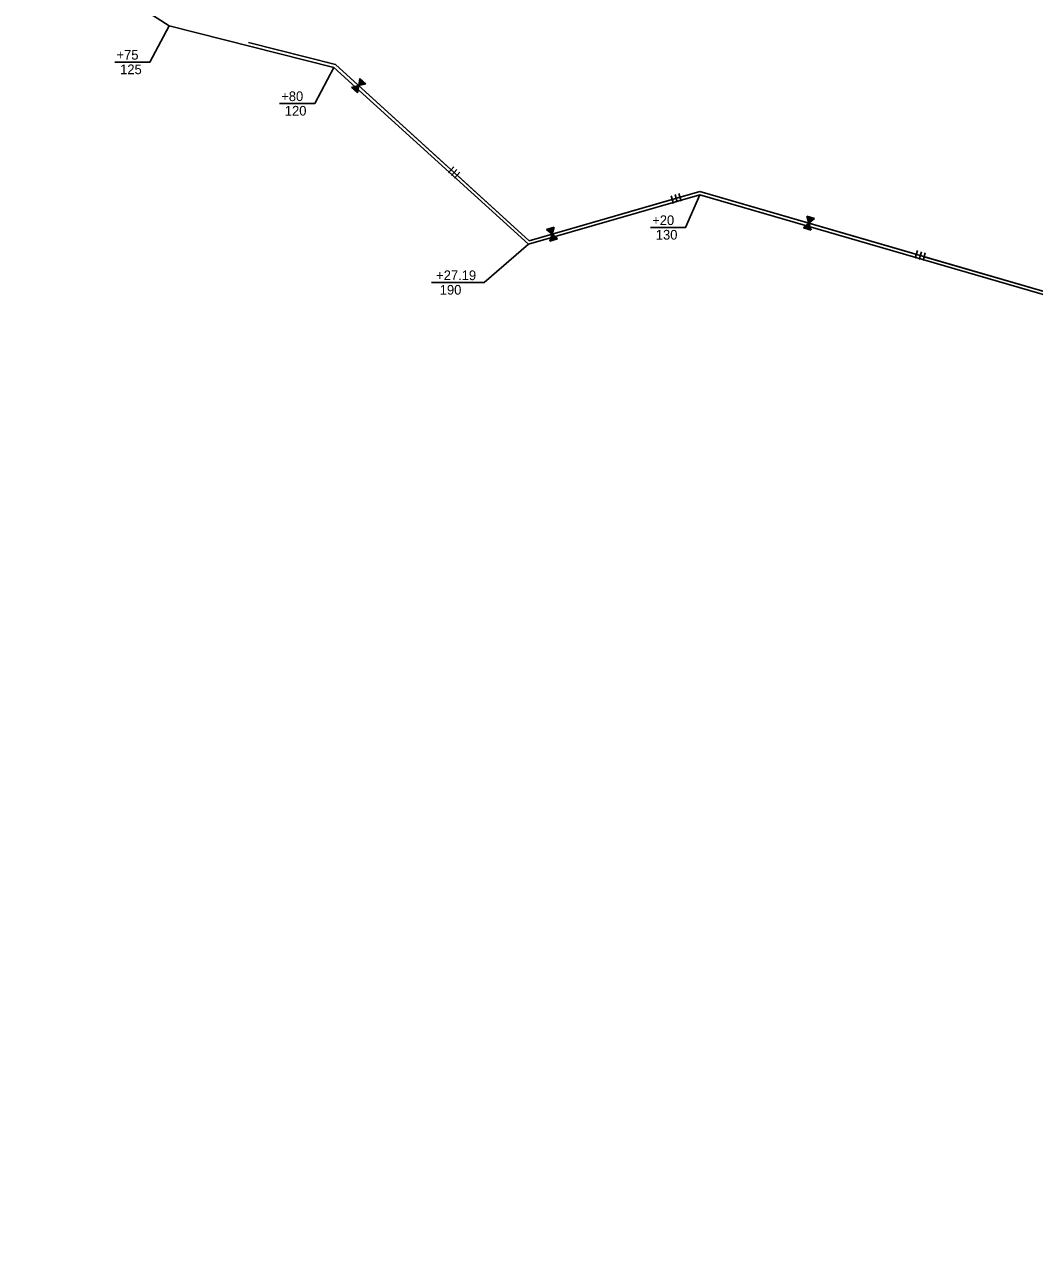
# Model space of a CAD drawing. Extents: x 979729 to 993523, y 1834148 to 1845433.
# Drawn here: x 981272 to 981898, y 1837610 to 1838364 of the extents above; entities that cross this region are included whole.
import ezdxf

# ---------------------------------------------------------------- set-up
doc = ezdxf.new("R2010")
doc.units = 0
for name, color, linetype in [('42', 7, 'Continuous'), ('51', 7, 'Continuous'), ('R_Draft', 7, 'Continuous')]:
    doc.layers.add(name, color=color, linetype=linetype)

msp = doc.modelspace()

# ---------------------------------------------------------------- linework, layer by layer
at = {"layer": '42'}
for p, q in [((981411.34, 1838352.61), (981465.14, 1838339.09)), ((981465.14, 1838339.09), (981585.3, 1838229.88)), ((981475.22, 1838324.86), (981479.59, 1838325.95)), ((981475.82, 1838324.99), (981475.73, 1838324.39)), ((981476.08, 1838325.04), (981475.95, 1838324.19)), ((981476.35, 1838325.12), (981476.18, 1838323.99)), ((981476.61, 1838325.21), (981476.4, 1838323.78)), ((981476.87, 1838325.25), (981476.62, 1838323.58)), ((981477.12, 1838325.24), (981476.87, 1838323.55)), ((981477.39, 1838325.36), (981477.06, 1838323.18)), ((981477.65, 1838325.4), (981477.29, 1838322.98)), ((981477.92, 1838325.52), (981477.51, 1838322.77)), ((981478.18, 1838325.53), (981477.73, 1838322.57)), ((981478.45, 1838325.65), (981477.95, 1838322.37)), ((981478.71, 1838325.69), (981478.18, 1838322.17)), ((981478.97, 1838325.78), (981478.4, 1838321.97)), ((981479.23, 1838325.8), (981478.62, 1838321.76)), ((981479.5, 1838325.91), (981478.84, 1838321.56)), ((981479.59, 1838325.95), (981478.92, 1838321.5)), ((981480.26, 1838330.41), (981479.59, 1838325.95)), ((981479.59, 1838325.95), (981483.96, 1838327.05)), ((981479.62, 1838326.05), (981483.89, 1838327.11)), ((981479.7, 1838326.58), (981483.44, 1838327.52)), ((981479.71, 1838326.33), (981483.67, 1838327.31)), ((981479.76, 1838326.85), (981483.22, 1838327.72)), ((981479.78, 1838327.12), (981483, 1838327.92)), ((981479.86, 1838327.65), (981482.55, 1838328.32)), ((981479.87, 1838327.4), (981482.78, 1838328.12)), ((981479.95, 1838327.93), (981482.33, 1838328.53)), ((981479.97, 1838328.19), (981482.11, 1838328.73)), ((981480.03, 1838328.72), (981481.66, 1838329.13)), ((981480.05, 1838328.99), (981481.44, 1838329.33)), ((981480.07, 1838328.48), (981481.73, 1838328.89)), ((981480.11, 1838329.26), (981481.22, 1838329.54)), ((981480.17, 1838329.53), (981481, 1838329.74)), ((981480.19, 1838329.79), (981480.78, 1838329.94)), ((981480.25, 1838330.07), (981480.55, 1838330.14)), ((981480.27, 1838330.33), (981480.33, 1838330.35)), ((981475.3, 1838324.86), (981475.29, 1838324.8)), ((981475.56, 1838324.91), (981475.51, 1838324.59)), ((981538.62, 1838275.68), (981535.26, 1838271.98)), ((981540.47, 1838274), (981537.11, 1838270.3)), ((981542.32, 1838272.31), (981538.96, 1838268.61)), ((981585.3, 1838229.88), (981690.99, 1838260.28)), ((981673.17, 1838257.76), (981674.55, 1838252.96)), ((981675.57, 1838258.45), (981676.96, 1838253.65)), ((981677.98, 1838259.14), (981679.36, 1838254.34)), ((981690.99, 1838260.28), (982114.9, 1838137.28)), ((981757.2, 1838244.98), (981758.56, 1838240.68)), ((981757.24, 1838244.91), (981757.29, 1838244.95)), ((981757.34, 1838244.66), (981757.58, 1838244.87)), ((981757.41, 1838244.39), (981757.87, 1838244.78)), ((981757.5, 1838244.15), (981758.16, 1838244.7)), ((981757.57, 1838243.87), (981758.45, 1838244.61)), ((981757.64, 1838243.6), (981758.74, 1838244.53)), ((981757.73, 1838243.36), (981759.02, 1838244.45)), ((981757.88, 1838243.16), (981759.19, 1838244.26)), ((981757.92, 1838242.86), (981759.6, 1838244.28)), ((981758.01, 1838242.61), (981759.89, 1838244.2)), ((981758.06, 1838242.33), (981760.18, 1838244.11)), ((981758.18, 1838242.1), (981760.47, 1838244.03)), ((981758.22, 1838241.81), (981760.76, 1838243.94)), ((981758.32, 1838241.57), (981761.04, 1838243.86)), ((981758.38, 1838241.29), (981761.33, 1838243.78)), ((981758.5, 1838241.07), (981761.62, 1838243.69)), ((981758.55, 1838240.78), (981761.91, 1838243.61)), ((981758.56, 1838240.68), (981762.01, 1838243.58)), ((981595.94, 1838236.84), (981599.38, 1838233.93)), ((981596.01, 1838236.81), (981596.03, 1838236.87)), ((981596.23, 1838236.65), (981596.32, 1838236.95)), ((981596.43, 1838236.46), (981596.61, 1838237.04)), ((981596.64, 1838236.3), (981596.9, 1838237.12)), ((981596.84, 1838236.11), (981597.19, 1838237.2)), ((981597.04, 1838235.92), (981597.48, 1838237.29)), ((981597.25, 1838235.76), (981597.76, 1838237.37)), ((981597.49, 1838235.66), (981598, 1838237.29)), ((981597.67, 1838235.44), (981598.34, 1838237.53)), ((981597.89, 1838235.28), (981598.63, 1838237.62)), ((981598.08, 1838235.06), (981598.92, 1838237.7)), ((981598.3, 1838234.93), (981599.21, 1838237.78)), ((981598.49, 1838234.71), (981599.5, 1838237.87)), ((981598.71, 1838234.55), (981599.79, 1838237.95)), ((981598.91, 1838234.36), (981600.07, 1838238.03)), ((981599.13, 1838234.23), (981600.36, 1838238.12)), ((981599.32, 1838234.01), (981600.65, 1838238.2)), ((981599.38, 1838233.93), (981600.75, 1838238.23)), ((981755.11, 1838237.77), (981758.56, 1838240.68)), ((981755.18, 1838237.81), (981755.2, 1838237.75)), ((981755.4, 1838237.96), (981755.49, 1838237.66)), ((981755.6, 1838238.16), (981755.78, 1838237.58)), ((981755.81, 1838238.31), (981756.07, 1838237.5)), ((981756.01, 1838238.51), (981756.36, 1838237.41)), ((981756.21, 1838238.7), (981756.65, 1838237.33)), ((981756.43, 1838238.86), (981756.93, 1838237.24)), ((981756.66, 1838238.95), (981757.17, 1838237.32)), ((981756.85, 1838239.18), (981757.51, 1838237.08)), ((981757.06, 1838239.33), (981757.8, 1838236.99)), ((981757.25, 1838239.55), (981758.09, 1838236.91)), ((981757.48, 1838239.68), (981758.38, 1838236.83)), ((981757.67, 1838239.9), (981758.67, 1838236.74)), ((981757.88, 1838240.06), (981758.95, 1838236.66)), ((981758.08, 1838240.25), (981759.24, 1838236.57)), ((981758.3, 1838240.38), (981759.53, 1838236.49)), ((981758.5, 1838240.6), (981759.82, 1838236.41)), ((981758.56, 1838240.68), (981759.91, 1838236.38)), ((981598.02, 1838229.64), (981599.38, 1838233.93)), ((981598.06, 1838229.71), (981598.11, 1838229.66)), ((981598.15, 1838229.95), (981598.4, 1838229.75)), ((981598.22, 1838230.22), (981598.68, 1838229.83)), ((981598.32, 1838230.47), (981598.97, 1838229.91)), ((981598.38, 1838230.74), (981599.26, 1838229.99)), ((981598.45, 1838231.01), (981599.55, 1838230.08)), ((981598.55, 1838231.25), (981599.84, 1838230.16)), ((981598.7, 1838231.46), (981600, 1838230.35)), ((981598.73, 1838231.75), (981600.42, 1838230.33)), ((981598.83, 1838232), (981600.71, 1838230.41)), ((981598.88, 1838232.28), (981600.99, 1838230.49)), ((981599, 1838232.51), (981601.28, 1838230.58)), ((981599.04, 1838232.8), (981601.57, 1838230.66)), ((981599.14, 1838233.05), (981601.86, 1838230.74)), ((981599.21, 1838233.32), (981602.15, 1838230.83)), ((981599.33, 1838233.54), (981602.44, 1838230.91)), ((981599.37, 1838233.83), (981602.73, 1838230.99)), ((981599.38, 1838233.93), (981602.82, 1838231.02)), ((981825.83, 1838223.76), (981824.44, 1838218.96)), ((981828.23, 1838223.06), (981826.84, 1838218.26)), ((981830.63, 1838222.37), (981829.24, 1838217.57))]:
    msp.add_line(p, q, dxfattribs=at)
for points in [[(981411.34, 1838352.61), (981465.14, 1838339.09), (981535.09, 1838275.51)], [(981480.26, 1838330.41), (981483.96, 1838327.05)], [(981475.22, 1838324.86), (981478.92, 1838321.5)], [(981540.64, 1838270.46), (981585.3, 1838229.88), (981671.46, 1838254.67)], [(981678.67, 1838256.74), (981690.99, 1838260.28)], [(981690.99, 1838260.28), (981822.73, 1838222.06)], [(981757.2, 1838244.98), (981762.01, 1838243.58)], [(981595.94, 1838236.84), (981600.75, 1838238.23)], [(981755.11, 1838237.77), (981759.91, 1838236.38)], [(981598.02, 1838229.64), (981602.82, 1838231.02)], [(981829.94, 1838219.97), (981973.99, 1838178.17)]]:
    msp.add_lwpolyline(points, dxfattribs=at)
at = {"layer": '51'}
for points in [[(981272.43, 1838420.68), (981362.11, 1838362.92), (981464.16, 1838337.27), (981584.78, 1838227.65)], [(983832.14, 1837610.35), (983652.57, 1837707.14), (983510.47, 1837676.41), (983408.2, 1837770.04), (983207.39, 1837710.64), (983118.6, 1837831.53), (982865.15, 1837788.06), (982600.28, 1837983.11), (982196.59, 1837995.54), (982113.58, 1838135.58), (981690.98, 1838258.2), (981584.78, 1838227.65)]]:
    msp.add_lwpolyline(points, dxfattribs=at)
at = {"layer": 'R_Draft'}
for p, q in [((981328.47, 1838340.52), (981344.27, 1838340.52)), ((981430.52, 1838314.87), (981446.32, 1838314.87)), ((981660.35, 1838238.05), (981676.15, 1838238.05)), ((981551.31, 1838203.94), (981524.72, 1838203.94))]:
    msp.add_line(p, q, dxfattribs=at)
for points in [[(981362.11, 1838362.92), (981350.27, 1838340.52), (981344.27, 1838340.52)], [(981464.16, 1838337.27), (981452.32, 1838314.87), (981446.32, 1838314.87)], [(981690.98, 1838258.2), (981682.15, 1838238.05), (981676.15, 1838238.05)], [(981584.78, 1838227.65), (981557.31, 1838203.94), (981551.31, 1838203.94)]]:
    msp.add_lwpolyline(points, dxfattribs=at)

# ---------------------------------------------------------------- texts
for s, p in [('+75', (981329.55, 1838342.02)), (' 125', (981329.55, 1838333.02)), ('+80', (981431.6, 1838316.37)), (' 120', (981431.6, 1838307.37)), ('+20', (981661.43, 1838239.55)), (' 130', (981661.43, 1838230.55)), ('+27.19', (981527.58, 1838205.44)), (' 190', (981527.58, 1838196.44))]:
    msp.add_text(s, height=6, rotation=360, dxfattribs=at).set_placement(p)

doc.saveas('drawing.dxf')
